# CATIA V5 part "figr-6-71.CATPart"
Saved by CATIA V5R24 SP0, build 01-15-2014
Part number: Part1
Bounding box of the stored display mesh (mm): x -44.666 to 106.759, y -69.79 to 69.79, z 0 to 74
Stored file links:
  D:\KAVITA\CATIA V5-6R2014 Project_ Kavita\CATIA V5-6R2014_partfiles\Partfiles\c06_catia_v5-6r2014_prt\figr-6-71.CATPart
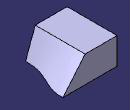
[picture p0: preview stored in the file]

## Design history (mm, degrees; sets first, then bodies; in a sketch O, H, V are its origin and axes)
Body1 (main body)
  Sketch1 on xy-plane, origin (0, 0, 0), H (1, 0, 0), V (0, 1, 0)
    line L1 (44.6658, 69.7903) -> (44.6658, -69.7903)
    line L2 (44.6658, -69.7903) -> (-44.6658, -69.7903)
    line L3 (-44.6658, -69.7903) -> (-44.6658, 69.7903)
    line L4 (-44.6658, 69.7903) -> (44.6658, 69.7903)
    vertical: L1 V, L3 V
    horizontal: L2 H, L4 H
    equidistance: L1 L3 O, L2 L4 O
  Pad1: profile Sketch1, direction (0, 0, 1), length 74
  Draft1: Angle 30, Neutral face of Pad1, PullDir face of Pad1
